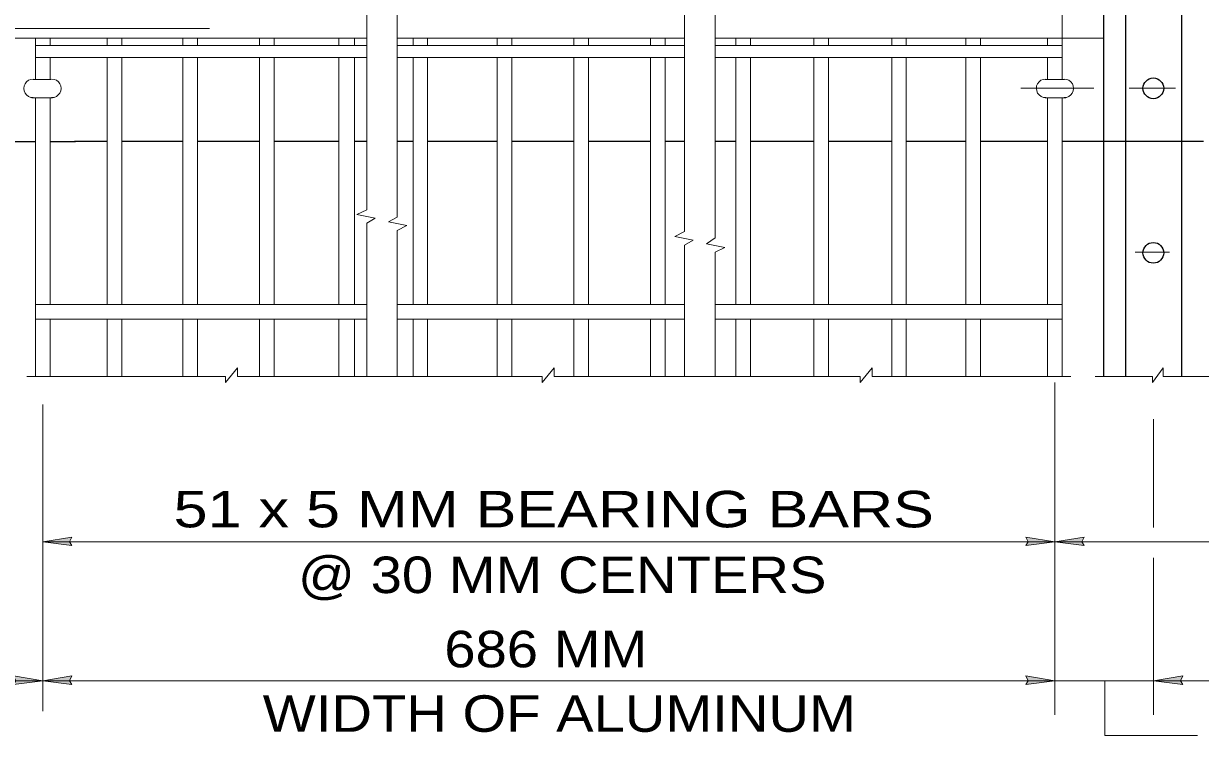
# Model space of a CAD drawing. Extents: x 312601.858 to 312602.699, y 144420.109 to 144420.704.
# Drawn here: x 312602.0138 to 312602.1105, y 144420.2481 to 144420.3066 of the extents above; entities that cross this region are included whole.
import ezdxf
from ezdxf.enums import TextEntityAlignment as Align

# ---------------------------------------------------------------- set-up
doc = ezdxf.new("R2010")
doc.units = 0
doc.header["$LTSCALE"] = 0.0012
doc.linetypes.add('DOT_DASHED', pattern=[7.7, 5, -1.2, 0.3, -1.2])
doc.linetypes.add('LONG_DASHED', pattern=[7.5, 6, -1.5])
for name, color, linetype, lineweight in [('1', 7, 'Continuous', 13), ('2', 7, 'Continuous', 13), ('39', 7, 'Continuous', 13)]:
    doc.layers.add(name, color=color, linetype=linetype, lineweight=lineweight)

msp = doc.modelspace()

# ---------------------------------------------------------------- hatches: boundary and pattern name
at = {"layer": '39'}
for points in [[(312602.0176, 144420.264), (312602.0178, 144420.2637), (312602.0154, 144420.264), (312602.0178, 144420.2644)], [(312602.0963, 144420.264), (312602.0961, 144420.2644), (312602.0985, 144420.264), (312602.0961, 144420.2637)], [(312602.1007, 144420.264), (312602.1009, 144420.2637), (312602.0985, 144420.264), (312602.1009, 144420.2644)], [(312602.0132, 144420.2526), (312602.013, 144420.253), (312602.0154, 144420.2526), (312602.013, 144420.2523)], [(312602.0176, 144420.2526), (312602.0178, 144420.2523), (312602.0154, 144420.2526), (312602.0178, 144420.253)], [(312602.0963, 144420.2526), (312602.0961, 144420.253), (312602.0985, 144420.2526), (312602.0961, 144420.2523)], [(312602.1088, 144420.2526), (312602.109, 144420.2523), (312602.1066, 144420.2526), (312602.109, 144420.253)]]:
    msp.add_hatch(color=256, dxfattribs=at).paths.add_polyline_path(points)

# ---------------------------------------------------------------- linework, layer by layer
at = {"layer": '1', "linetype": 'DOT_DASHED'}
for p, q in [((312602.1066, 144420.4253), (312602.1066, 144420.2757)), ((312601.9291, 144420.3062), (312602.114, 144420.3062)), ((312602.0957, 144420.3013), (312602.1017, 144420.3013)), ((312602.1046, 144420.3013), (312602.1084, 144420.3013))]:
    msp.add_line(p, q, dxfattribs=at)
at = {"layer": '1', "lineweight": 25}
for p, q in [((312602.1025, 144420.3468), (312602.1025, 144420.2776)), ((312602.1043, 144420.336), (312602.1043, 144420.2776)), ((312602.1089, 144420.336), (312602.1089, 144420.2776)), ((312602.0081, 144420.2969), (312602.0148, 144420.2969)), ((312602.016, 144420.2969), (312602.0181, 144420.2969)), ((312602.0207, 144420.2969), (312602.018, 144420.2969)), ((312602.0269, 144420.2969), (312602.0219, 144420.2969)), ((312602.0332, 144420.2969), (312602.0281, 144420.2969)), ((312602.0397, 144420.2969), (312602.0344, 144420.2969)), ((312602.042, 144420.2969), (312602.041, 144420.2969)), ((312602.0458, 144420.2969), (312602.0445, 144420.2969)), ((312602.0527, 144420.2969), (312602.047, 144420.2969)), ((312602.059, 144420.2969), (312602.0539, 144420.2969)), ((312602.0653, 144420.2969), (312602.0602, 144420.2969)), ((312602.0681, 144420.2969), (312602.0665, 144420.2969)), ((312602.0723, 144420.2969), (312602.0706, 144420.2969)), ((312602.0787, 144420.2969), (312602.0735, 144420.2969)), ((312602.0851, 144420.2969), (312602.0799, 144420.2969)), ((312602.0912, 144420.2969), (312602.0863, 144420.2969)), ((312602.0979, 144420.2969), (312602.0924, 144420.2969)), ((312602.1025, 144420.2969), (312602.0991, 144420.2969))]:
    msp.add_line(p, q, dxfattribs=at)
at = {"layer": '1'}
for p, q in [((312602.042, 144420.323), (312602.042, 144420.2913)), ((312602.0445, 144420.3221), (312602.0445, 144420.2907)), ((312602.0681, 144420.3212), (312602.0681, 144420.2895)), ((312602.0706, 144420.3203), (312602.0706, 144420.289)), ((312602.0991, 144420.302), (312602.0991, 144420.3104)), ((312602.0148, 144420.3054), (312602.0148, 144420.3022)), ((312602.016, 144420.3048), (312602.016, 144420.3054)), ((312602.0207, 144420.3048), (312602.0207, 144420.3054)), ((312602.0219, 144420.3048), (312602.0219, 144420.3054)), ((312602.0269, 144420.3048), (312602.0269, 144420.3054)), ((312602.0281, 144420.3048), (312602.0281, 144420.3054)), ((312602.0332, 144420.3048), (312602.0332, 144420.3054)), ((312602.0344, 144420.3048), (312602.0344, 144420.3054)), ((312602.0397, 144420.3048), (312602.0397, 144420.3054)), ((312602.041, 144420.3048), (312602.041, 144420.3054)), ((312602.0458, 144420.3048), (312602.0458, 144420.3054)), ((312602.047, 144420.3048), (312602.047, 144420.3054)), ((312602.0527, 144420.3048), (312602.0527, 144420.3054)), ((312602.0539, 144420.3048), (312602.0539, 144420.3054)), ((312602.059, 144420.3048), (312602.059, 144420.3054)), ((312602.0602, 144420.3048), (312602.0602, 144420.3054)), ((312602.0653, 144420.3048), (312602.0653, 144420.3054)), ((312602.0665, 144420.3048), (312602.0665, 144420.3054)), ((312602.0723, 144420.3048), (312602.0723, 144420.3054)), ((312602.0735, 144420.3048), (312602.0735, 144420.3054)), ((312602.0787, 144420.3048), (312602.0787, 144420.3054)), ((312602.0799, 144420.3048), (312602.0799, 144420.3054)), ((312602.0851, 144420.3048), (312602.0851, 144420.3054)), ((312602.0863, 144420.3048), (312602.0863, 144420.3054)), ((312602.0912, 144420.3048), (312602.0912, 144420.3054)), ((312602.0924, 144420.3048), (312602.0924, 144420.3054)), ((312602.0979, 144420.3048), (312602.0979, 144420.3054)), ((312602.0148, 144420.3048), (312602.042, 144420.3048)), ((312602.0445, 144420.3048), (312602.0681, 144420.3048)), ((312602.0706, 144420.3048), (312602.0991, 144420.3048)), ((312602.0148, 144420.302), (312602.0148, 144420.3038)), ((312602.0148, 144420.3038), (312602.042, 144420.3038)), ((312602.016, 144420.302), (312602.016, 144420.3038)), ((312602.0207, 144420.2835), (312602.0207, 144420.3038)), ((312602.0219, 144420.2835), (312602.0219, 144420.3038)), ((312602.0269, 144420.2835), (312602.0269, 144420.3038)), ((312602.0281, 144420.2835), (312602.0281, 144420.3038)), ((312602.0332, 144420.2835), (312602.0332, 144420.3038)), ((312602.0344, 144420.2835), (312602.0344, 144420.3038)), ((312602.0397, 144420.2835), (312602.0397, 144420.3038)), ((312602.041, 144420.2835), (312602.041, 144420.3038)), ((312602.0445, 144420.3038), (312602.0681, 144420.3038)), ((312602.0458, 144420.2835), (312602.0458, 144420.3038)), ((312602.047, 144420.2835), (312602.047, 144420.3038)), ((312602.0527, 144420.2835), (312602.0527, 144420.3038)), ((312602.0539, 144420.2835), (312602.0539, 144420.3038)), ((312602.059, 144420.2835), (312602.059, 144420.3038)), ((312602.0602, 144420.2835), (312602.0602, 144420.3038)), ((312602.0653, 144420.2835), (312602.0653, 144420.3038)), ((312602.0665, 144420.2835), (312602.0665, 144420.3038)), ((312602.0706, 144420.3038), (312602.0991, 144420.3038)), ((312602.0723, 144420.2835), (312602.0723, 144420.3038)), ((312602.0735, 144420.2835), (312602.0735, 144420.3038)), ((312602.0787, 144420.2835), (312602.0787, 144420.3038)), ((312602.0799, 144420.2835), (312602.0799, 144420.3038)), ((312602.0851, 144420.2835), (312602.0851, 144420.3038)), ((312602.0863, 144420.2835), (312602.0863, 144420.3038)), ((312602.0912, 144420.2835), (312602.0912, 144420.3038)), ((312602.0924, 144420.2835), (312602.0924, 144420.3038)), ((312602.0979, 144420.302), (312602.0979, 144420.3038)), ((312602.0146, 144420.302), (312602.0161, 144420.302)), ((312602.0977, 144420.302), (312602.0993, 144420.302)), ((312602.0145, 144420.3005), (312602.0162, 144420.3005)), ((312602.0148, 144420.2776), (312602.0148, 144420.3005)), ((312602.016, 144420.2835), (312602.016, 144420.3005)), ((312602.0977, 144420.3005), (312602.0994, 144420.3005)), ((312602.0979, 144420.2835), (312602.0979, 144420.3005)), ((312602.0991, 144420.2776), (312602.0991, 144420.3005)), ((312602.0412, 144420.2909), (312602.042, 144420.2913)), ((312602.0412, 144420.2909), (312602.0427, 144420.2906)), ((312602.042, 144420.2902), (312602.0427, 144420.2906)), ((312602.042, 144420.2902), (312602.042, 144420.2776)), ((312602.0438, 144420.2903), (312602.0445, 144420.2907)), ((312602.0438, 144420.2903), (312602.0453, 144420.29)), ((312602.0445, 144420.2896), (312602.0453, 144420.29)), ((312602.0445, 144420.2896), (312602.0445, 144420.2776)), ((312602.0673, 144420.2891), (312602.0681, 144420.2895)), ((312602.0673, 144420.2891), (312602.0688, 144420.2888)), ((312602.0681, 144420.2884), (312602.0688, 144420.2888)), ((312602.0699, 144420.2885), (312602.0706, 144420.289)), ((312602.0681, 144420.2884), (312602.0681, 144420.2776)), ((312602.0699, 144420.2885), (312602.0714, 144420.2882)), ((312602.0706, 144420.2878), (312602.0714, 144420.2882)), ((312602.0706, 144420.2878), (312602.0706, 144420.2776)), ((312602.1051, 144420.2878), (312602.1079, 144420.2878)), ((312602.0148, 144420.2835), (312602.042, 144420.2835)), ((312602.0445, 144420.2835), (312602.0681, 144420.2835)), ((312602.0706, 144420.2835), (312602.0991, 144420.2835)), ((312602.0148, 144420.2823), (312602.042, 144420.2823)), ((312602.016, 144420.2776), (312602.016, 144420.2823)), ((312602.0207, 144420.2776), (312602.0207, 144420.2823)), ((312602.0219, 144420.2776), (312602.0219, 144420.2823)), ((312602.0269, 144420.2776), (312602.0269, 144420.2823)), ((312602.0281, 144420.2776), (312602.0281, 144420.2823)), ((312602.0332, 144420.2776), (312602.0332, 144420.2823)), ((312602.0344, 144420.2776), (312602.0344, 144420.2823)), ((312602.0397, 144420.2776), (312602.0397, 144420.2823)), ((312602.041, 144420.2776), (312602.041, 144420.2823)), ((312602.0445, 144420.2823), (312602.0681, 144420.2823)), ((312602.0458, 144420.2776), (312602.0458, 144420.2823)), ((312602.047, 144420.2776), (312602.047, 144420.2823)), ((312602.0527, 144420.2776), (312602.0527, 144420.2823)), ((312602.0539, 144420.2776), (312602.0539, 144420.2823)), ((312602.059, 144420.2776), (312602.059, 144420.2823)), ((312602.0602, 144420.2776), (312602.0602, 144420.2823)), ((312602.0653, 144420.2776), (312602.0653, 144420.2823)), ((312602.0665, 144420.2776), (312602.0665, 144420.2823)), ((312602.0706, 144420.2823), (312602.0991, 144420.2823)), ((312602.0723, 144420.2776), (312602.0723, 144420.2823)), ((312602.0735, 144420.2776), (312602.0735, 144420.2823)), ((312602.0787, 144420.2776), (312602.0787, 144420.2823)), ((312602.0799, 144420.2776), (312602.0799, 144420.2823)), ((312602.0851, 144420.2776), (312602.0851, 144420.2823)), ((312602.0863, 144420.2776), (312602.0863, 144420.2823)), ((312602.0912, 144420.2776), (312602.0912, 144420.2823)), ((312602.0924, 144420.2776), (312602.0924, 144420.2823)), ((312602.0979, 144420.2776), (312602.0979, 144420.2823)), ((312602.0304, 144420.2771), (312602.0314, 144420.2783)), ((312602.0314, 144420.2776), (312602.0314, 144420.2783)), ((312602.0564, 144420.2771), (312602.0574, 144420.2783)), ((312602.0574, 144420.2776), (312602.0574, 144420.2783)), ((312602.0825, 144420.2771), (312602.0835, 144420.2783)), ((312602.0835, 144420.2776), (312602.0835, 144420.2783)), ((312602.1065, 144420.2771), (312602.1074, 144420.2783)), ((312602.1074, 144420.2776), (312602.1074, 144420.2783)), ((312602.0141, 144420.2776), (312602.0304, 144420.2776)), ((312602.0304, 144420.2771), (312602.0304, 144420.2776)), ((312602.0314, 144420.2776), (312602.041, 144420.2776)), ((312602.041, 144420.2776), (312602.0564, 144420.2776)), ((312602.0564, 144420.2771), (312602.0564, 144420.2776)), ((312602.0574, 144420.2776), (312602.0825, 144420.2776)), ((312602.0825, 144420.2771), (312602.0825, 144420.2776)), ((312602.0835, 144420.2776), (312602.0998, 144420.2776)), ((312602.1018, 144420.2776), (312602.1065, 144420.2776)), ((312602.1065, 144420.2771), (312602.1065, 144420.2776)), ((312602.1074, 144420.2776), (312602.1124, 144420.2776)), ((312602.0154, 144420.2727), (312602.0154, 144420.2501)), ((312602.0985, 144420.2727), (312602.0985, 144420.2498)), ((312602.1066, 144420.2727), (312602.1066, 144420.2652)), ((312602.1066, 144420.2627), (312602.1066, 144420.2529)), ((312602.0574, 144420.2526), (312602.0825, 144420.2526)), ((312602.0985, 144420.2526), (312602.1066, 144420.2526)), ((312602.1066, 144420.2529), (312602.1066, 144420.2498))]:
    msp.add_line(p, q, dxfattribs=at)
at = {"layer": '1', "linetype": 'LONG_DASHED'}
for p, q in [((312602.0081, 144420.3054), (312602.042, 144420.3054)), ((312602.0445, 144420.3054), (312602.0681, 144420.3054)), ((312602.0706, 144420.3054), (312602.1025, 144420.3054))]:
    msp.add_line(p, q, dxfattribs=at)
at = {"layer": '1', "linetype": 'LONG_DASHED', "lineweight": 25}
msp.add_line((312602.1107, 144420.2969), (312602.1025, 144420.2969), dxfattribs=at)
at = {"layer": '1'}
for points in [[(312602.0985, 144420.2771), (312602.0985, 144420.2727), (312602.0985, 144420.2704)], [(312602.0154, 144420.2753), (312602.0154, 144420.2727), (312602.0154, 144420.2704)], [(312602.1066, 144420.2741), (312602.1066, 144420.2727), (312602.1066, 144420.2704)], [(312602.0154, 144420.264), (312602.0985, 144420.264), (312602.1466, 144420.264)], [(312601.9335, 144420.2526), (312601.9611, 144420.2526), (312601.9927, 144420.2526), (312602.0154, 144420.2526), (312602.0985, 144420.2526)], [(312602.1066, 144420.2526), (312602.2356, 144420.2526), (312602.2461, 144420.2526)]]:
    msp.add_lwpolyline(points, dxfattribs=at)
at = {"layer": '1', "lineweight": 25}
for centre in [(312602.10658, 144420.301275), (312602.10658, 144420.28776)]:
    msp.add_circle(centre, 0.00085, dxfattribs=at)
at = {"layer": '1'}
for centre, start, end in [((312602.01461, 144420.301275), 90, 270.77834), ((312602.01614, 144420.301275), 269.22166, 90), ((312602.09774, 144420.301275), 90, 270.77834), ((312602.09927, 144420.301275), 269.22166, 90)]:
    msp.add_arc(centre, 0.000765, start, end, dxfattribs=at)
at = {"layer": '2'}
for p in [(312602.1026, 144420.2526), (312602.1102, 144420.2481)]:
    msp.add_line(p, (312602.1026, 144420.2481), dxfattribs=at)
at = {"layer": '39'}
for points in [[(312602.0176, 144420.264), (312602.0178, 144420.2637), (312602.0154, 144420.264), (312602.0178, 144420.2644)], [(312602.0963, 144420.264), (312602.0961, 144420.2644), (312602.0985, 144420.264), (312602.0961, 144420.2637)], [(312602.1007, 144420.264), (312602.1009, 144420.2637), (312602.0985, 144420.264), (312602.1009, 144420.2644)], [(312602.0132, 144420.2526), (312602.013, 144420.253), (312602.0154, 144420.2526), (312602.013, 144420.2523)], [(312602.0176, 144420.2526), (312602.0178, 144420.2523), (312602.0154, 144420.2526), (312602.0178, 144420.253)], [(312602.0963, 144420.2526), (312602.0961, 144420.253), (312602.0985, 144420.2526), (312602.0961, 144420.2523)], [(312602.1088, 144420.2526), (312602.109, 144420.2523), (312602.1066, 144420.2526), (312602.109, 144420.253)]]:
    msp.add_lwpolyline(points, close=True, dxfattribs=at)

# ---------------------------------------------------------------- texts
at = {"layer": '2'}
for s, width, p in [('51 x 5 MM BEARING BARS ', 1.25, (312602.05805, 144420.2652)), ('@ 30 MM CENTERS', 1.15, (312602.05805, 144420.2598)), ('686 MM', 1.15, (312602.0567, 144420.2537)), ('WIDTH OF ALUMINUM ', 1.15, (312602.05845, 144420.2484))]:
    msp.add_text(s, height=0.003, dxfattribs=dict(at, width=width)).set_placement(p, align=Align.CENTER)

doc.saveas('drawing.dxf')
